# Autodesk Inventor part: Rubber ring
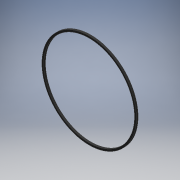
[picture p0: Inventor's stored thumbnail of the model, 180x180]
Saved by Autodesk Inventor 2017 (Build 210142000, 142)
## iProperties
Created: 2020-03
Part Number: Rubber ring
Material: Rubber, Silicone
Document SubType Name: Modeling
Designer: user
Density: 1.25 g/cm^3
Appearance: Rubber - Black
Author: user
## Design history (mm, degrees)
sketch "Sketch1"
  geometry: C1 r 99 at (0, 0); C2 r 103 at (0, 0); 1 further point
  constraints: 2 centre point, 1 coincident
  dimensions: "d0" = 198 diameter of C1; "d1" = 4 radial gap between concentric circles of C1 C2
extrude "Extrusion1" new body sketch "Sketch1" distance "d2" = 4; taper "d3" = 0 deg
body "Solid1"
